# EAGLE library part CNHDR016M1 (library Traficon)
16 pins Header 2x8 - 2mm - 17,35mm high (MALE)
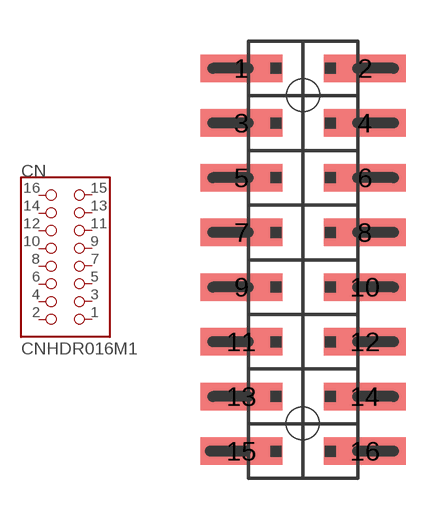
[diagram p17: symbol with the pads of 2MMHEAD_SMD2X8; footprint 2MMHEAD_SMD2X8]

Designator prefix CN

## CNHDR016M1  [2MMHEAD_SMD2X8]
1  1  pas
2  2  pas
3  3  pas
4  4  pas
5  5  pas
6  6  pas
7  7  pas
8  8  pas
9  9  pas
10  10  pas
11  11  pas
12  12  pas
13  13  pas
14  14  pas
15  15  pas
16  16  pas

## Footprint 2MMHEAD_SMD2X8 (pad centres in mm)
CT: 2/04/08: rotated component 180°, because it's more logical to have the first pin on the top left.
smd 3 x 1: 1 -2.26,7; 2 2.26,7; 3 -2.26,5; 4 2.26,5; 5 -2.26,3; 6 2.26,3; 7 -2.26,1; 8 2.26,1; 9 -2.26,-1; 10 2.26,-1; 11 -2.26,-3; 12 2.26,-3; 13 -2.26,-5; 14 2.26,-5; 15 -2.26,-7; 16 2.26,-7
hole 1.2 at -0.02,-5.98
hole 1.2 at 0,6.02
